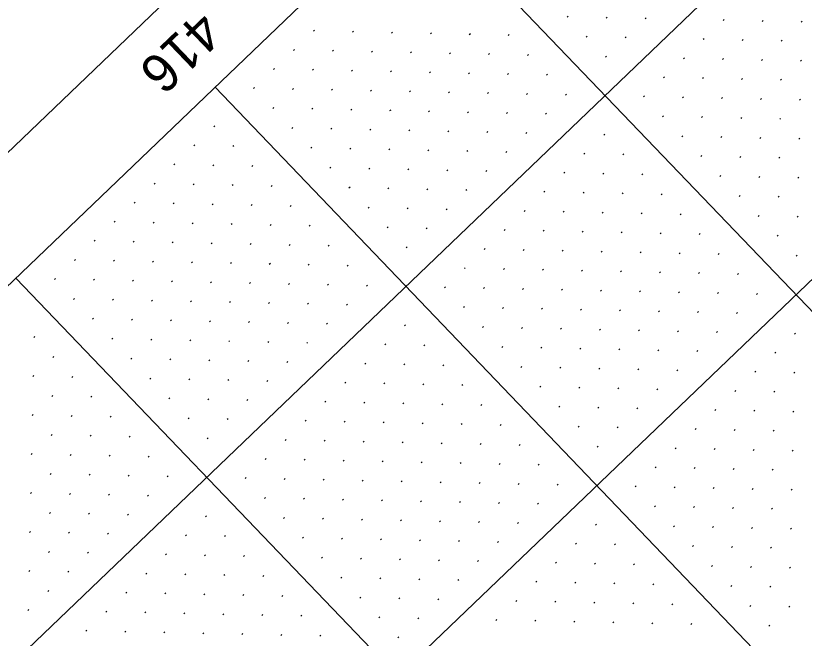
# Model space of a CAD drawing. Extents: x 2148987 to 2151117, y 142806 to 144993.
# Drawn here: x 2149370 to 2149512.9, y 143833.4 to 143946.3 of the extents above; entities that cross this region are included whole.
import ezdxf

# ---------------------------------------------------------------- set-up
doc = ezdxf.new("R2010")
doc.units = 0
for name, color, linetype in [('PR_PIER_PH3', 7, 'Continuous'), ('PR_Road_Concrete', 7, 'Continuous'), ('SHT_Profile_Grid_Minor', 7, 'Continuous'), ('Wall D Bore Txt', 7, 'Continuous')]:
    doc.layers.add(name, color=color, linetype=linetype)

msp = doc.modelspace()

# ---------------------------------------------------------------- linework, layer by layer
at = {"layer": 'PR_PIER_PH3'}
for p, q in [((2150261.97, 144684.26), (2149124.83, 143594.52)), ((2150296.56, 144648.16), (2149159.43, 143558.42)), ((2149442.21, 143967.92), (2149788.16, 143606.92)), ((2149406.11, 143933.32), (2149752.06, 143572.33)), ((2149370.01, 143898.73), (2149715.96, 143537.73))]:
    msp.add_line(p, q, dxfattribs=at)
at = {"layer": 'PR_Road_Concrete'}
msp.add_line((2150227.37, 144720.36), (2149279.76, 143812.24), dxfattribs=at)
msp.add_lwpolyline([(2150941.76, 143974.91), (2149804.63, 142885.16), (2149078.13, 143643.25), (2150215.26, 144733)], close=True, dxfattribs=at)
at = {"layer": 'SHT_Profile_Grid_Minor'}
for p, q in [((2149470.12, 143946.2), (2149469.94, 143946.02)), ((2149477.19, 143946.05), (2149477.01, 143945.87)), ((2149484.26, 143945.89), (2149484.08, 143945.72)), ((2149498.4, 143945.59), (2149498.22, 143945.42)), ((2149505.47, 143945.44), (2149505.29, 143945.27)), ((2149512.54, 143945.29), (2149512.36, 143945.12)), ((2149424.1, 143943.64), (2149423.92, 143943.47)), ((2149431.17, 143943.49), (2149430.99, 143943.32)), ((2149438.24, 143943.34), (2149438.06, 143943.16)), ((2149445.31, 143943.19), (2149445.13, 143943.01)), ((2149452.38, 143943.04), (2149452.19, 143942.86)), ((2149459.44, 143942.89), (2149459.26, 143942.71)), ((2149473.58, 143942.59), (2149473.4, 143942.41)), ((2149480.65, 143942.44), (2149480.47, 143942.26)), ((2149494.79, 143942.13), (2149494.61, 143941.96)), ((2149501.86, 143941.98), (2149501.68, 143941.81)), ((2149508.93, 143941.83), (2149508.75, 143941.66)), ((2149420.49, 143940.18), (2149420.31, 143940.01)), ((2149427.56, 143940.03), (2149427.38, 143939.86)), ((2149434.63, 143939.88), (2149434.45, 143939.71)), ((2149441.7, 143939.73), (2149441.52, 143939.55)), ((2149448.77, 143939.58), (2149448.58, 143939.4)), ((2149455.83, 143939.43), (2149455.65, 143939.25)), ((2149462.9, 143939.28), (2149462.72, 143939.1)), ((2149477.04, 143938.98), (2149476.86, 143938.8)), ((2149491.18, 143938.67), (2149491, 143938.5)), ((2149498.25, 143938.52), (2149498.07, 143938.35)), ((2149505.32, 143938.37), (2149505.14, 143938.2)), ((2149512.39, 143938.22), (2149512.21, 143938.05)), ((2149416.88, 143936.72), (2149416.7, 143936.55)), ((2149423.95, 143936.57), (2149423.77, 143936.4)), ((2149431.02, 143936.42), (2149430.84, 143936.25)), ((2149438.09, 143936.27), (2149437.91, 143936.1)), ((2149445.16, 143936.12), (2149444.97, 143935.94)), ((2149452.22, 143935.97), (2149452.04, 143935.79)), ((2149459.29, 143935.82), (2149459.11, 143935.64)), ((2149466.36, 143935.67), (2149466.18, 143935.49)), ((2149487.57, 143935.22), (2149487.39, 143935.04)), ((2149494.64, 143935.06), (2149494.46, 143934.89)), ((2149501.71, 143934.91), (2149501.53, 143934.74)), ((2149508.78, 143934.76), (2149508.6, 143934.59)), ((2149413.27, 143933.26), (2149413.09, 143933.09)), ((2149420.34, 143933.11), (2149420.16, 143932.94)), ((2149427.41, 143932.96), (2149427.23, 143932.79)), ((2149434.48, 143932.81), (2149434.3, 143932.64)), ((2149441.55, 143932.66), (2149441.36, 143932.49)), ((2149448.61, 143932.51), (2149448.43, 143932.33)), ((2149455.68, 143932.36), (2149455.5, 143932.18)), ((2149462.75, 143932.21), (2149462.57, 143932.03)), ((2149469.82, 143932.06), (2149469.64, 143931.88)), ((2149483.96, 143931.76), (2149483.78, 143931.58)), ((2149491.03, 143931.61), (2149490.85, 143931.43)), ((2149498.1, 143931.45), (2149497.92, 143931.28)), ((2149505.17, 143931.3), (2149504.99, 143931.13)), ((2149512.24, 143931.15), (2149512.06, 143930.98)), ((2149416.73, 143929.65), (2149416.55, 143929.48)), ((2149423.8, 143929.5), (2149423.62, 143929.33)), ((2149430.87, 143929.35), (2149430.69, 143929.18)), ((2149437.94, 143929.2), (2149437.75, 143929.03)), ((2149445, 143929.05), (2149444.82, 143928.88)), ((2149452.07, 143928.9), (2149451.89, 143928.72)), ((2149459.14, 143928.75), (2149458.96, 143928.57)), ((2149466.21, 143928.6), (2149466.03, 143928.42)), ((2149487.42, 143928.15), (2149487.24, 143927.97)), ((2149494.49, 143928), (2149494.31, 143927.82)), ((2149501.56, 143927.84), (2149501.38, 143927.67)), ((2149508.63, 143927.69), (2149508.45, 143927.52)), ((2149406.05, 143926.34), (2149405.87, 143926.17)), ((2149420.19, 143926.04), (2149420.01, 143925.87)), ((2149427.26, 143925.89), (2149427.08, 143925.72)), ((2149434.33, 143925.74), (2149434.15, 143925.57)), ((2149441.39, 143925.59), (2149441.21, 143925.42)), ((2149448.46, 143925.44), (2149448.28, 143925.27)), ((2149455.53, 143925.29), (2149455.35, 143925.12)), ((2149462.6, 143925.14), (2149462.42, 143924.96)), ((2149476.74, 143924.84), (2149476.56, 143924.66)), ((2149490.88, 143924.54), (2149490.7, 143924.36)), ((2149497.95, 143924.39), (2149497.77, 143924.21)), ((2149402.44, 143922.88), (2149402.26, 143922.71)), ((2149505.02, 143924.23), (2149504.84, 143924.06)), ((2149512.09, 143924.08), (2149511.91, 143923.91)), ((2149409.51, 143922.73), (2149409.33, 143922.56)), ((2149423.65, 143922.43), (2149423.47, 143922.26)), ((2149430.72, 143922.28), (2149430.54, 143922.11)), ((2149437.79, 143922.13), (2149437.6, 143921.96)), ((2149444.85, 143921.98), (2149444.67, 143921.81)), ((2149451.92, 143921.83), (2149451.74, 143921.66)), ((2149458.99, 143921.68), (2149458.81, 143921.51)), ((2149473.13, 143921.38), (2149472.95, 143921.2)), ((2149480.2, 143921.23), (2149480.02, 143921.05)), ((2149494.34, 143920.93), (2149494.16, 143920.75)), ((2149501.41, 143920.78), (2149501.23, 143920.6)), ((2149508.48, 143920.63), (2149508.3, 143920.45)), ((2149398.83, 143919.42), (2149398.65, 143919.25)), ((2149405.9, 143919.27), (2149405.72, 143919.1)), ((2149412.97, 143919.12), (2149412.79, 143918.95)), ((2149427.11, 143918.82), (2149426.93, 143918.65)), ((2149434.18, 143918.67), (2149433.99, 143918.5)), ((2149441.24, 143918.52), (2149441.06, 143918.35)), ((2149448.31, 143918.37), (2149448.13, 143918.2)), ((2149455.38, 143918.22), (2149455.2, 143918.05)), ((2149469.52, 143917.92), (2149469.34, 143917.74)), ((2149476.59, 143917.77), (2149476.41, 143917.59)), ((2149483.66, 143917.62), (2149483.48, 143917.44)), ((2149497.8, 143917.32), (2149497.62, 143917.14)), ((2149504.87, 143917.17), (2149504.69, 143916.99)), ((2149395.22, 143915.96), (2149395.04, 143915.79)), ((2149402.29, 143915.81), (2149402.11, 143915.64)), ((2149511.94, 143917.02), (2149511.76, 143916.84)), ((2149409.36, 143915.66), (2149409.18, 143915.49)), ((2149416.43, 143915.51), (2149416.25, 143915.34)), ((2149430.57, 143915.21), (2149430.38, 143915.04)), ((2149437.63, 143915.06), (2149437.45, 143914.89)), ((2149444.7, 143914.91), (2149444.52, 143914.74)), ((2149451.77, 143914.76), (2149451.59, 143914.59)), ((2149465.91, 143914.46), (2149465.73, 143914.29)), ((2149472.98, 143914.31), (2149472.8, 143914.13)), ((2149480.05, 143914.16), (2149479.87, 143913.98)), ((2149487.12, 143914.01), (2149486.94, 143913.83)), ((2149501.26, 143913.71), (2149501.08, 143913.53)), ((2149508.33, 143913.56), (2149508.15, 143913.38)), ((2149391.61, 143912.5), (2149391.43, 143912.33)), ((2149398.68, 143912.35), (2149398.5, 143912.18)), ((2149405.75, 143912.2), (2149405.57, 143912.03)), ((2149412.82, 143912.05), (2149412.64, 143911.88)), ((2149419.89, 143911.9), (2149419.71, 143911.73)), ((2149434.02, 143911.6), (2149433.84, 143911.43)), ((2149441.09, 143911.45), (2149440.91, 143911.28)), ((2149448.16, 143911.3), (2149447.98, 143911.13)), ((2149462.3, 143911), (2149462.12, 143910.83)), ((2149469.37, 143910.85), (2149469.19, 143910.68)), ((2149476.44, 143910.7), (2149476.26, 143910.52)), ((2149483.51, 143910.55), (2149483.33, 143910.37)), ((2149490.58, 143910.4), (2149490.4, 143910.22)), ((2149504.72, 143910.1), (2149504.54, 143909.92)), ((2149388, 143909.04), (2149387.82, 143908.87)), ((2149395.07, 143908.89), (2149394.89, 143908.72)), ((2149402.14, 143908.74), (2149401.96, 143908.57)), ((2149409.21, 143908.59), (2149409.03, 143908.42)), ((2149511.79, 143909.95), (2149511.61, 143909.77)), ((2149416.28, 143908.44), (2149416.1, 143908.27)), ((2149423.35, 143908.29), (2149423.16, 143908.12)), ((2149437.48, 143907.99), (2149437.3, 143907.82)), ((2149444.55, 143907.84), (2149444.37, 143907.67)), ((2149458.69, 143907.54), (2149458.51, 143907.37)), ((2149465.76, 143907.39), (2149465.58, 143907.22)), ((2149472.83, 143907.24), (2149472.65, 143907.07)), ((2149479.9, 143907.09), (2149479.72, 143906.91)), ((2149486.97, 143906.94), (2149486.79, 143906.76)), ((2149494.04, 143906.79), (2149493.86, 143906.61)), ((2149508.18, 143906.49), (2149508, 143906.31)), ((2149384.39, 143905.58), (2149384.21, 143905.41)), ((2149391.46, 143905.43), (2149391.28, 143905.26)), ((2149398.53, 143905.28), (2149398.35, 143905.11)), ((2149405.6, 143905.13), (2149405.42, 143904.96)), ((2149412.67, 143904.98), (2149412.49, 143904.81)), ((2149419.74, 143904.83), (2149419.55, 143904.66)), ((2149426.8, 143904.68), (2149426.62, 143904.51)), ((2149440.94, 143904.38), (2149440.76, 143904.21)), ((2149455.08, 143904.08), (2149454.9, 143903.91)), ((2149462.15, 143903.93), (2149461.97, 143903.76)), ((2149469.22, 143903.78), (2149469.04, 143903.61)), ((2149476.29, 143903.63), (2149476.11, 143903.46)), ((2149483.36, 143903.48), (2149483.18, 143903.3)), ((2149490.43, 143903.33), (2149490.25, 143903.15)), ((2149497.5, 143903.18), (2149497.32, 143903)), ((2149511.64, 143902.88), (2149511.46, 143902.7)), ((2149380.78, 143902.12), (2149380.6, 143901.95)), ((2149387.85, 143901.97), (2149387.67, 143901.8)), ((2149394.92, 143901.82), (2149394.74, 143901.65)), ((2149401.99, 143901.67), (2149401.81, 143901.5)), ((2149409.06, 143901.52), (2149408.88, 143901.35)), ((2149416.13, 143901.37), (2149415.94, 143901.2)), ((2149423.19, 143901.22), (2149423.01, 143901.05)), ((2149430.26, 143901.07), (2149430.08, 143900.9)), ((2149451.47, 143900.62), (2149451.29, 143900.45)), ((2149458.54, 143900.47), (2149458.36, 143900.3)), ((2149465.61, 143900.32), (2149465.43, 143900.15)), ((2149472.68, 143900.17), (2149472.5, 143900)), ((2149479.75, 143900.02), (2149479.57, 143899.85)), ((2149377.17, 143898.66), (2149376.99, 143898.49)), ((2149486.82, 143899.87), (2149486.64, 143899.69)), ((2149493.89, 143899.72), (2149493.71, 143899.54)), ((2149500.96, 143899.57), (2149500.78, 143899.39)), ((2149384.24, 143898.51), (2149384.06, 143898.34)), ((2149391.31, 143898.36), (2149391.13, 143898.19)), ((2149398.38, 143898.21), (2149398.2, 143898.04)), ((2149405.45, 143898.06), (2149405.27, 143897.89)), ((2149412.52, 143897.91), (2149412.33, 143897.74)), ((2149419.58, 143897.76), (2149419.4, 143897.59)), ((2149426.65, 143897.61), (2149426.47, 143897.44)), ((2149433.72, 143897.46), (2149433.54, 143897.29)), ((2149447.86, 143897.16), (2149447.68, 143896.99)), ((2149454.93, 143897.01), (2149454.75, 143896.84)), ((2149462, 143896.86), (2149461.82, 143896.69)), ((2149469.07, 143896.71), (2149468.89, 143896.54)), ((2149476.14, 143896.56), (2149475.96, 143896.39)), ((2149483.21, 143896.41), (2149483.03, 143896.24)), ((2149490.28, 143896.26), (2149490.1, 143896.08)), ((2149497.35, 143896.11), (2149497.17, 143895.93)), ((2149504.42, 143895.96), (2149504.24, 143895.78)), ((2149380.63, 143895.05), (2149380.45, 143894.88)), ((2149387.7, 143894.9), (2149387.52, 143894.73)), ((2149394.77, 143894.75), (2149394.59, 143894.58)), ((2149401.84, 143894.6), (2149401.66, 143894.43)), ((2149408.91, 143894.45), (2149408.72, 143894.28)), ((2149415.97, 143894.3), (2149415.79, 143894.13)), ((2149423.04, 143894.15), (2149422.86, 143893.98)), ((2149430.11, 143894), (2149429.93, 143893.83)), ((2149451.32, 143893.55), (2149451.14, 143893.38)), ((2149458.39, 143893.4), (2149458.21, 143893.23)), ((2149465.46, 143893.25), (2149465.28, 143893.08)), ((2149472.53, 143893.1), (2149472.35, 143892.93)), ((2149479.6, 143892.95), (2149479.42, 143892.78)), ((2149384.09, 143891.45), (2149383.91, 143891.27)), ((2149486.67, 143892.8), (2149486.49, 143892.63)), ((2149493.74, 143892.65), (2149493.56, 143892.48)), ((2149500.81, 143892.5), (2149500.63, 143892.32)), ((2149391.16, 143891.29), (2149390.98, 143891.12)), ((2149398.23, 143891.14), (2149398.05, 143890.97)), ((2149405.3, 143890.99), (2149405.11, 143890.82)), ((2149412.36, 143890.84), (2149412.18, 143890.67)), ((2149419.43, 143890.69), (2149419.25, 143890.52)), ((2149426.5, 143890.54), (2149426.32, 143890.37)), ((2149440.64, 143890.24), (2149440.46, 143890.07)), ((2149454.78, 143889.94), (2149454.6, 143889.77)), ((2149461.85, 143889.79), (2149461.67, 143889.62)), ((2149468.92, 143889.64), (2149468.74, 143889.47)), ((2149475.99, 143889.49), (2149475.81, 143889.32)), ((2149483.06, 143889.34), (2149482.88, 143889.17)), ((2149490.13, 143889.19), (2149489.95, 143889.02)), ((2149497.2, 143889.04), (2149497.02, 143888.87)), ((2149511.34, 143888.74), (2149511.16, 143888.56)), ((2149373.41, 143888.14), (2149373.23, 143887.96)), ((2149387.55, 143887.84), (2149387.37, 143887.66)), ((2149394.62, 143887.68), (2149394.44, 143887.51)), ((2149401.69, 143887.53), (2149401.51, 143887.36)), ((2149408.75, 143887.38), (2149408.57, 143887.21)), ((2149415.82, 143887.23), (2149415.64, 143887.06)), ((2149422.89, 143887.08), (2149422.71, 143886.91)), ((2149437.03, 143886.78), (2149436.85, 143886.61)), ((2149444.1, 143886.63), (2149443.92, 143886.46)), ((2149458.24, 143886.33), (2149458.06, 143886.16)), ((2149465.31, 143886.18), (2149465.13, 143886.01)), ((2149472.38, 143886.03), (2149472.2, 143885.86)), ((2149479.45, 143885.88), (2149479.27, 143885.71)), ((2149486.52, 143885.73), (2149486.34, 143885.56)), ((2149376.87, 143884.53), (2149376.69, 143884.35)), ((2149493.59, 143885.58), (2149493.41, 143885.41)), ((2149507.73, 143885.28), (2149507.55, 143885.1)), ((2149391.01, 143884.23), (2149390.83, 143884.05)), ((2149398.08, 143884.07), (2149397.9, 143883.9)), ((2149405.15, 143883.92), (2149404.96, 143883.75)), ((2149412.21, 143883.77), (2149412.03, 143883.6)), ((2149419.28, 143883.62), (2149419.1, 143883.45)), ((2149433.42, 143883.32), (2149433.24, 143883.15)), ((2149440.49, 143883.17), (2149440.31, 143883)), ((2149447.56, 143883.02), (2149447.38, 143882.85)), ((2149461.7, 143882.72), (2149461.52, 143882.55)), ((2149468.77, 143882.57), (2149468.59, 143882.4)), ((2149475.84, 143882.42), (2149475.66, 143882.25)), ((2149482.91, 143882.27), (2149482.73, 143882.1)), ((2149489.98, 143882.12), (2149489.8, 143881.95)), ((2149504.12, 143881.82), (2149503.94, 143881.65)), ((2149511.19, 143881.67), (2149511.01, 143881.49)), ((2149373.26, 143881.07), (2149373.08, 143880.89)), ((2149380.33, 143880.92), (2149380.15, 143880.74)), ((2149394.47, 143880.62), (2149394.29, 143880.44)), ((2149401.54, 143880.46), (2149401.35, 143880.29)), ((2149408.6, 143880.31), (2149408.42, 143880.14)), ((2149415.67, 143880.16), (2149415.49, 143879.99)), ((2149429.81, 143879.86), (2149429.63, 143879.69)), ((2149436.88, 143879.71), (2149436.7, 143879.54)), ((2149443.95, 143879.56), (2149443.77, 143879.39)), ((2149451.02, 143879.41), (2149450.84, 143879.24)), ((2149465.16, 143879.11), (2149464.98, 143878.94)), ((2149472.23, 143878.96), (2149472.05, 143878.79)), ((2149479.3, 143878.81), (2149479.12, 143878.64)), ((2149486.37, 143878.66), (2149486.19, 143878.49)), ((2149376.72, 143877.46), (2149376.54, 143877.28)), ((2149383.79, 143877.31), (2149383.61, 143877.13)), ((2149500.51, 143878.36), (2149500.33, 143878.19)), ((2149507.58, 143878.21), (2149507.4, 143878.04)), ((2149397.93, 143877.01), (2149397.74, 143876.83)), ((2149404.99, 143876.85), (2149404.81, 143876.68)), ((2149412.06, 143876.7), (2149411.88, 143876.53)), ((2149426.2, 143876.4), (2149426.02, 143876.23)), ((2149433.27, 143876.25), (2149433.09, 143876.08)), ((2149440.34, 143876.1), (2149440.16, 143875.93)), ((2149447.41, 143875.95), (2149447.23, 143875.78)), ((2149454.48, 143875.8), (2149454.3, 143875.63)), ((2149468.62, 143875.5), (2149468.44, 143875.33)), ((2149475.69, 143875.35), (2149475.51, 143875.18)), ((2149482.76, 143875.2), (2149482.58, 143875.03)), ((2149496.9, 143874.9), (2149496.72, 143874.73)), ((2149503.97, 143874.75), (2149503.79, 143874.58)), ((2149511.04, 143874.6), (2149510.86, 143874.43)), ((2149373.11, 143874), (2149372.93, 143873.82)), ((2149380.18, 143873.85), (2149380, 143873.67)), ((2149387.25, 143873.7), (2149387.07, 143873.52)), ((2149401.38, 143873.4), (2149401.2, 143873.22)), ((2149408.45, 143873.24), (2149408.27, 143873.07)), ((2149422.59, 143872.94), (2149422.41, 143872.77)), ((2149429.66, 143872.79), (2149429.48, 143872.62)), ((2149436.73, 143872.64), (2149436.55, 143872.47)), ((2149443.8, 143872.49), (2149443.62, 143872.32)), ((2149450.87, 143872.34), (2149450.69, 143872.17)), ((2149457.94, 143872.19), (2149457.76, 143872.02)), ((2149472.08, 143871.89), (2149471.9, 143871.72)), ((2149479.15, 143871.74), (2149478.97, 143871.57)), ((2149493.29, 143871.44), (2149493.11, 143871.27)), ((2149376.57, 143870.39), (2149376.39, 143870.21)), ((2149383.64, 143870.24), (2149383.46, 143870.06)), ((2149390.71, 143870.09), (2149390.52, 143869.91)), ((2149500.36, 143871.29), (2149500.18, 143871.12)), ((2149507.43, 143871.14), (2149507.25, 143870.97)), ((2149404.84, 143869.79), (2149404.66, 143869.61)), ((2149418.98, 143869.48), (2149418.8, 143869.31)), ((2149426.05, 143869.33), (2149425.87, 143869.16)), ((2149433.12, 143869.18), (2149432.94, 143869.01)), ((2149440.19, 143869.03), (2149440.01, 143868.86)), ((2149447.26, 143868.88), (2149447.08, 143868.71)), ((2149454.33, 143868.73), (2149454.15, 143868.56)), ((2149461.4, 143868.58), (2149461.22, 143868.41)), ((2149475.54, 143868.28), (2149475.36, 143868.11)), ((2149489.68, 143867.98), (2149489.5, 143867.81)), ((2149496.75, 143867.83), (2149496.57, 143867.66)), ((2149503.82, 143867.68), (2149503.64, 143867.51)), ((2149510.89, 143867.53), (2149510.71, 143867.36)), ((2149372.96, 143866.93), (2149372.78, 143866.75)), ((2149380.03, 143866.78), (2149379.85, 143866.6)), ((2149387.1, 143866.63), (2149386.91, 143866.45)), ((2149394.16, 143866.48), (2149393.98, 143866.3)), ((2149415.37, 143866.02), (2149415.19, 143865.85)), ((2149422.44, 143865.87), (2149422.26, 143865.7)), ((2149429.51, 143865.72), (2149429.33, 143865.55)), ((2149436.58, 143865.57), (2149436.4, 143865.4)), ((2149443.65, 143865.42), (2149443.47, 143865.25)), ((2149450.72, 143865.27), (2149450.54, 143865.1)), ((2149457.79, 143865.12), (2149457.61, 143864.95)), ((2149464.86, 143864.97), (2149464.68, 143864.8)), ((2149486.07, 143864.52), (2149485.89, 143864.35)), ((2149493.14, 143864.37), (2149492.96, 143864.2)), ((2149376.42, 143863.32), (2149376.24, 143863.14)), ((2149383.49, 143863.17), (2149383.3, 143862.99)), ((2149390.55, 143863.02), (2149390.37, 143862.84)), ((2149397.62, 143862.87), (2149397.44, 143862.69)), ((2149500.21, 143864.22), (2149500.03, 143864.05)), ((2149507.28, 143864.07), (2149507.1, 143863.9)), ((2149411.76, 143862.57), (2149411.58, 143862.39)), ((2149418.83, 143862.41), (2149418.65, 143862.24)), ((2149425.9, 143862.26), (2149425.72, 143862.09)), ((2149432.97, 143862.11), (2149432.79, 143861.94)), ((2149440.04, 143861.96), (2149439.86, 143861.79)), ((2149447.11, 143861.81), (2149446.93, 143861.64)), ((2149454.18, 143861.66), (2149454, 143861.49)), ((2149461.25, 143861.51), (2149461.07, 143861.34)), ((2149468.32, 143861.36), (2149468.14, 143861.19)), ((2149482.46, 143861.06), (2149482.28, 143860.89)), ((2149489.53, 143860.91), (2149489.35, 143860.74)), ((2149496.6, 143860.76), (2149496.42, 143860.59)), ((2149503.67, 143860.61), (2149503.49, 143860.44)), ((2149510.74, 143860.46), (2149510.56, 143860.29)), ((2149372.81, 143859.86), (2149372.63, 143859.69)), ((2149379.88, 143859.71), (2149379.69, 143859.53)), ((2149386.94, 143859.56), (2149386.76, 143859.38)), ((2149394.01, 143859.41), (2149393.83, 143859.23)), ((2149415.22, 143858.96), (2149415.04, 143858.78)), ((2149422.29, 143858.81), (2149422.11, 143858.63)), ((2149429.36, 143858.65), (2149429.18, 143858.48)), ((2149436.43, 143858.5), (2149436.25, 143858.33)), ((2149443.5, 143858.35), (2149443.32, 143858.18)), ((2149450.57, 143858.2), (2149450.39, 143858.03)), ((2149457.64, 143858.05), (2149457.46, 143857.88)), ((2149464.71, 143857.9), (2149464.53, 143857.73)), ((2149485.92, 143857.45), (2149485.74, 143857.28)), ((2149492.99, 143857.3), (2149492.81, 143857.13)), ((2149500.06, 143857.15), (2149499.88, 143856.98)), ((2149376.27, 143856.25), (2149376.08, 143856.08)), ((2149383.33, 143856.1), (2149383.15, 143855.92)), ((2149390.4, 143855.95), (2149390.22, 143855.77)), ((2149507.13, 143857), (2149506.95, 143856.83)), ((2149404.54, 143855.65), (2149404.36, 143855.47)), ((2149418.68, 143855.35), (2149418.5, 143855.17)), ((2149425.75, 143855.2), (2149425.57, 143855.02)), ((2149432.82, 143855.04), (2149432.64, 143854.87)), ((2149439.89, 143854.89), (2149439.71, 143854.72)), ((2149446.96, 143854.74), (2149446.78, 143854.57)), ((2149454.03, 143854.59), (2149453.85, 143854.42)), ((2149461.1, 143854.44), (2149460.92, 143854.27)), ((2149475.24, 143854.14), (2149475.06, 143853.97)), ((2149489.38, 143853.84), (2149489.2, 143853.67)), ((2149496.45, 143853.69), (2149496.27, 143853.52)), ((2149503.52, 143853.54), (2149503.34, 143853.37)), ((2149510.59, 143853.39), (2149510.4, 143853.22)), ((2149372.66, 143852.79), (2149372.47, 143852.62)), ((2149379.72, 143852.64), (2149379.54, 143852.47)), ((2149386.79, 143852.49), (2149386.61, 143852.31)), ((2149400.93, 143852.19), (2149400.75, 143852.01)), ((2149408, 143852.04), (2149407.82, 143851.86)), ((2149422.14, 143851.74), (2149421.96, 143851.56)), ((2149429.21, 143851.59), (2149429.03, 143851.41)), ((2149436.28, 143851.43), (2149436.1, 143851.26)), ((2149443.35, 143851.28), (2149443.17, 143851.11)), ((2149450.42, 143851.13), (2149450.24, 143850.96)), ((2149457.49, 143850.98), (2149457.31, 143850.81)), ((2149471.63, 143850.68), (2149471.45, 143850.51)), ((2149478.7, 143850.53), (2149478.52, 143850.36)), ((2149492.84, 143850.23), (2149492.66, 143850.06)), ((2149499.91, 143850.08), (2149499.73, 143849.91)), ((2149376.11, 143849.18), (2149375.93, 143849.01)), ((2149383.18, 143849.03), (2149383, 143848.86)), ((2149397.32, 143848.73), (2149397.14, 143848.55)), ((2149404.39, 143848.58), (2149404.21, 143848.4)), ((2149506.98, 143849.93), (2149506.79, 143849.76)), ((2149411.46, 143848.43), (2149411.28, 143848.25)), ((2149425.6, 143848.13), (2149425.42, 143847.95)), ((2149432.67, 143847.98), (2149432.49, 143847.8)), ((2149439.74, 143847.82), (2149439.56, 143847.65)), ((2149446.81, 143847.67), (2149446.63, 143847.5)), ((2149453.88, 143847.52), (2149453.7, 143847.35)), ((2149468.02, 143847.22), (2149467.84, 143847.05)), ((2149475.09, 143847.07), (2149474.91, 143846.9)), ((2149372.5, 143845.72), (2149372.32, 143845.55)), ((2149482.16, 143846.92), (2149481.98, 143846.75)), ((2149496.3, 143846.62), (2149496.12, 143846.45)), ((2149503.37, 143846.47), (2149503.18, 143846.3)), ((2149510.43, 143846.32), (2149510.25, 143846.15)), ((2149379.57, 143845.57), (2149379.39, 143845.4)), ((2149393.71, 143845.27), (2149393.53, 143845.09)), ((2149400.78, 143845.12), (2149400.6, 143844.94)), ((2149407.85, 143844.97), (2149407.67, 143844.79)), ((2149414.92, 143844.82), (2149414.74, 143844.64)), ((2149429.06, 143844.52), (2149428.88, 143844.34)), ((2149436.13, 143844.37), (2149435.95, 143844.19)), ((2149443.2, 143844.21), (2149443.02, 143844.04)), ((2149450.27, 143844.06), (2149450.09, 143843.89)), ((2149464.41, 143843.76), (2149464.23, 143843.59)), ((2149471.48, 143843.61), (2149471.3, 143843.44)), ((2149478.55, 143843.46), (2149478.37, 143843.29)), ((2149485.62, 143843.31), (2149485.44, 143843.14)), ((2149499.76, 143843.01), (2149499.57, 143842.84)), ((2149506.82, 143842.86), (2149506.64, 143842.69)), ((2149375.96, 143842.11), (2149375.78, 143841.94)), ((2149390.1, 143841.81), (2149389.92, 143841.64)), ((2149397.17, 143841.66), (2149396.99, 143841.48)), ((2149404.24, 143841.51), (2149404.06, 143841.33)), ((2149411.31, 143841.36), (2149411.13, 143841.18)), ((2149418.38, 143841.21), (2149418.2, 143841.03)), ((2149432.52, 143840.91), (2149432.34, 143840.73)), ((2149439.59, 143840.76), (2149439.41, 143840.58)), ((2149446.66, 143840.6), (2149446.48, 143840.43)), ((2149460.8, 143840.3), (2149460.62, 143840.13)), ((2149467.87, 143840.15), (2149467.69, 143839.98)), ((2149474.94, 143840), (2149474.76, 143839.83)), ((2149372.35, 143838.65), (2149372.17, 143838.48)), ((2149482.01, 143839.85), (2149481.83, 143839.68)), ((2149489.08, 143839.7), (2149488.9, 143839.53)), ((2149503.21, 143839.4), (2149503.03, 143839.23)), ((2149510.28, 143839.25), (2149510.1, 143839.08)), ((2149386.49, 143838.35), (2149386.31, 143838.18)), ((2149393.56, 143838.2), (2149393.38, 143838.03)), ((2149400.63, 143838.05), (2149400.45, 143837.87)), ((2149407.7, 143837.9), (2149407.52, 143837.72)), ((2149414.77, 143837.75), (2149414.59, 143837.57)), ((2149421.84, 143837.6), (2149421.66, 143837.42)), ((2149435.98, 143837.3), (2149435.8, 143837.12)), ((2149443.05, 143837.15), (2149442.87, 143836.97)), ((2149457.19, 143836.84), (2149457.01, 143836.67)), ((2149464.26, 143836.69), (2149464.08, 143836.52)), ((2149471.33, 143836.54), (2149471.15, 143836.37)), ((2149478.4, 143836.39), (2149478.22, 143836.22)), ((2149485.47, 143836.24), (2149485.29, 143836.07)), ((2149492.54, 143836.09), (2149492.35, 143835.92)), ((2149506.67, 143835.79), (2149506.49, 143835.62)), ((2149382.88, 143834.89), (2149382.7, 143834.72)), ((2149389.95, 143834.74), (2149389.77, 143834.57)), ((2149397.02, 143834.59), (2149396.84, 143834.42)), ((2149404.09, 143834.44), (2149403.91, 143834.26)), ((2149411.16, 143834.29), (2149410.98, 143834.11)), ((2149418.23, 143834.14), (2149418.05, 143833.96)), ((2149425.3, 143833.99), (2149425.12, 143833.81)), ((2149439.44, 143833.69), (2149439.26, 143833.51))]:
    msp.add_line(p, q, dxfattribs=at)

# ---------------------------------------------------------------- texts
at = {"layer": 'Wall D Bore Txt'}
msp.add_text('416', height=7, rotation=223.7809, dxfattribs=at).set_placement((2149403.24, 143947.54))

doc.saveas('drawing.dxf')
